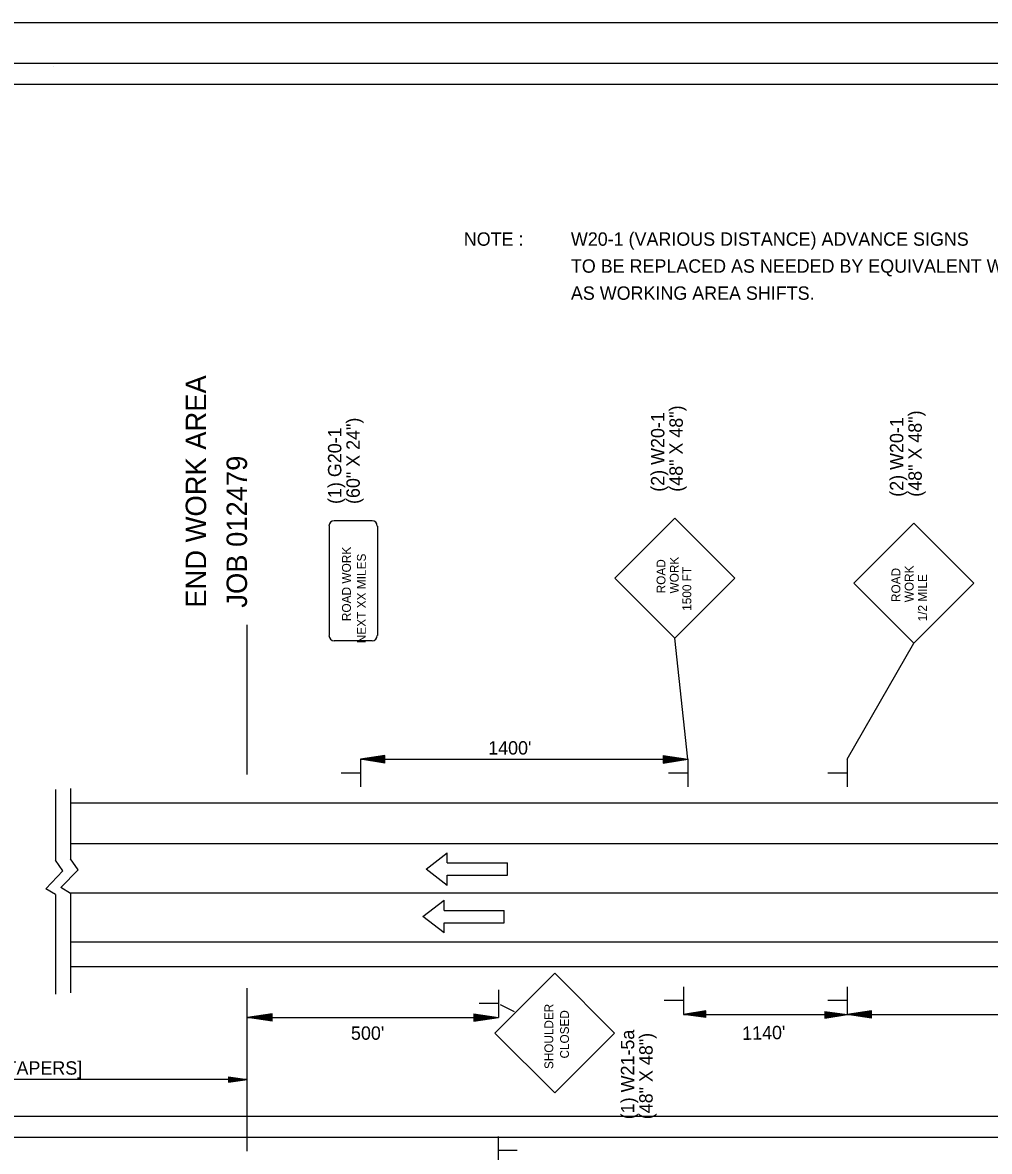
# Model space of a CAD drawing. Extents: x 1373222 to 1374279, y 380783 to 380996.
# Drawn here: x 1373384 to 1373476.4, y 380888.5 to 380996.5 of the extents above; entities that cross this region are included whole.
import ezdxf

# ---------------------------------------------------------------- set-up
doc = ezdxf.new("R2010")
doc.units = 0
for name, color, linetype in [('R_Border', 7, 'Continuous'), ('R_Border Plan-Plan', 7, 'Continuous'), ('R_Draft', 7, 'Continuous'), ('R_No Plot', 7, 'Continuous')]:
    doc.layers.add(name, color=color, linetype=linetype)

msp = doc.modelspace()

# ---------------------------------------------------------------- linework, layer by layer
at = {"layer": 'R_Border'}
for p, q in [((1373234.38, 380992.59), (1373550.56, 380992.59)), ((1373386.9, 380992.33), (1373386.9, 380992.33)), ((1373386.9, 380992.33), (1373386.9, 380992.33))]:
    msp.add_line(p, q, dxfattribs=at)
at = {"layer": 'R_Border Plan-Plan'}
msp.add_line((1373234.38, 380889.86), (1373550.56, 380889.86), dxfattribs=at)
at = {"layer": 'R_Draft'}
for p, q in [((1373417.39, 380948.84), (1373413.78, 380948.84)), ((1373446.36, 380949.08), (1373440.62, 380943.35)), ((1373446.36, 380949.08), (1373452.09, 380943.35)), ((1373469.2, 380948.61), (1373463.47, 380942.88)), ((1373469.2, 380948.61), (1373474.93, 380942.88)), ((1373413.28, 380948.33), (1373413.28, 380937.85)), ((1373417.9, 380948.33), (1373417.9, 380937.85)), ((1373440.62, 380943.35), (1373446.36, 380937.61)), ((1373452.09, 380943.35), (1373446.36, 380937.61)), ((1373463.47, 380942.88), (1373469.2, 380937.14)), ((1373474.93, 380942.88), (1373469.2, 380937.14)), ((1373405.44, 380924.56), (1373405.44, 380938.87)), ((1373417.39, 380937.35), (1373413.78, 380937.35)), ((1373447.58, 380926.02), (1373446.36, 380937.61)), ((1373462.83, 380926.02), (1373469.2, 380937.14)), ((1373418.63, 380926.37), (1373416.28, 380926.02)), ((1373416.28, 380926.02), (1373416.28, 380923.38)), ((1373416.28, 380926.02), (1373447.58, 380926.02)), ((1373418.63, 380925.66), (1373416.28, 380926.02)), ((1373418.63, 380926.31), (1373416.67, 380926.02)), ((1373418.63, 380925.72), (1373416.67, 380926.02)), ((1373418.63, 380926.25), (1373417.08, 380926.02)), ((1373418.63, 380925.78), (1373417.08, 380926.02)), ((1373418.63, 380926.19), (1373417.47, 380926.02)), ((1373418.63, 380925.84), (1373417.47, 380926.02)), ((1373418.63, 380926.13), (1373417.87, 380926.02)), ((1373418.63, 380925.9), (1373417.87, 380926.02)), ((1373418.63, 380926.07), (1373418.26, 380926.02)), ((1373418.63, 380925.96), (1373418.26, 380926.02)), ((1373418.63, 380925.66), (1373418.63, 380926.37)), ((1373445.23, 380926.37), (1373447.58, 380926.02)), ((1373445.23, 380926.37), (1373445.23, 380925.66)), ((1373445.23, 380926.31), (1373447.18, 380926.02)), ((1373445.23, 380926.25), (1373446.78, 380926.02)), ((1373445.23, 380926.19), (1373446.39, 380926.02)), ((1373445.23, 380926.13), (1373445.99, 380926.02)), ((1373445.23, 380926.07), (1373445.6, 380926.02)), ((1373445.23, 380925.66), (1373447.58, 380926.02)), ((1373445.23, 380925.9), (1373445.99, 380926.02)), ((1373445.23, 380925.78), (1373446.78, 380926.02)), ((1373445.23, 380925.72), (1373447.18, 380926.02)), ((1373445.23, 380925.84), (1373446.39, 380926.02)), ((1373445.23, 380925.96), (1373445.6, 380926.02)), ((1373447.58, 380926.02), (1373447.58, 380923.38)), ((1373462.83, 380926.02), (1373462.83, 380923.38)), ((1373416.24, 380924.7), (1373414.44, 380924.7)), ((1373447.54, 380924.7), (1373445.74, 380924.7)), ((1373462.79, 380924.7), (1373460.99, 380924.7)), ((1373387.11, 380923.14), (1373387.11, 380916.38)), ((1373388.56, 380923.24), (1373388.56, 380916.49)), ((1373407.82, 380921.83), (1373388.56, 380921.83)), ((1373492.92, 380921.83), (1373407.82, 380921.83)), ((1373407.82, 380917.92), (1373388.56, 380917.92)), ((1373492.92, 380917.92), (1373407.82, 380917.92)), ((1373422.56, 380915.51), (1373424.59, 380917.07)), ((1373424.59, 380916.1), (1373424.59, 380917.07)), ((1373424.59, 380916.1), (1373430.34, 380916.1)), ((1373430.34, 380914.92), (1373430.34, 380916.1)), ((1373424.59, 380913.95), (1373422.56, 380915.51)), ((1373424.59, 380914.92), (1373430.34, 380914.92)), ((1373424.59, 380913.95), (1373424.59, 380914.92)), ((1373387.11, 380913.09), (1373387.11, 380903.56)), ((1373407.82, 380913.22), (1373388.5, 380913.22)), ((1373388.56, 380913.19), (1373388.56, 380903.67)), ((1373492.92, 380913.22), (1373407.82, 380913.22)), ((1373422.25, 380910.98), (1373424.28, 380912.54)), ((1373424.28, 380911.56), (1373424.28, 380912.54)), ((1373424.28, 380909.41), (1373422.25, 380910.98)), ((1373424.28, 380911.56), (1373430.04, 380911.56)), ((1373430.04, 380910.39), (1373430.04, 380911.56)), ((1373424.28, 380910.39), (1373430.04, 380910.39)), ((1373424.28, 380909.41), (1373424.28, 380910.39)), ((1373407.82, 380908.53), (1373388.56, 380908.53)), ((1373492.92, 380908.53), (1373407.82, 380908.53)), ((1373407.82, 380906.18), (1373388.56, 380906.18)), ((1373492.92, 380906.18), (1373407.82, 380906.18)), ((1373434.86, 380905.57), (1373429.13, 380899.83)), ((1373434.86, 380905.57), (1373440.59, 380899.83)), ((1373447.18, 380904.25), (1373447.18, 380901.61)), ((1373462.83, 380904.25), (1373462.83, 380901.61)), ((1373405.44, 380888.52), (1373405.44, 380904.12)), ((1373429.48, 380903.97), (1373429.48, 380901.33)), ((1373429.44, 380902.66), (1373427.64, 380902.66)), ((1373429.65, 380902.57), (1373431, 380901.88)), ((1373447.14, 380902.94), (1373445.34, 380902.94)), ((1373462.79, 380902.94), (1373460.99, 380902.94)), ((1373407.83, 380901.68), (1373405.48, 380901.33)), ((1373405.48, 380901.33), (1373429.48, 380901.33)), ((1373407.83, 380900.98), (1373405.48, 380901.33)), ((1373407.83, 380901.62), (1373405.87, 380901.33)), ((1373407.83, 380901.04), (1373405.87, 380901.33)), ((1373407.83, 380901.56), (1373406.28, 380901.33)), ((1373407.83, 380901.1), (1373406.28, 380901.33)), ((1373407.83, 380901.5), (1373406.67, 380901.33)), ((1373407.83, 380901.15), (1373406.67, 380901.33)), ((1373407.83, 380901.44), (1373407.07, 380901.33)), ((1373407.83, 380901.22), (1373407.07, 380901.33)), ((1373407.83, 380901.38), (1373407.46, 380901.33)), ((1373407.83, 380901.27), (1373407.46, 380901.33)), ((1373407.83, 380900.98), (1373407.83, 380901.68)), ((1373427.13, 380901.68), (1373429.48, 380901.33)), ((1373427.13, 380901.68), (1373427.13, 380900.98)), ((1373427.13, 380901.62), (1373429.09, 380901.33)), ((1373427.13, 380901.56), (1373428.68, 380901.33)), ((1373427.13, 380901.5), (1373428.29, 380901.33)), ((1373427.13, 380901.44), (1373427.89, 380901.33)), ((1373427.13, 380901.38), (1373427.5, 380901.33)), ((1373427.13, 380900.98), (1373429.48, 380901.33)), ((1373427.13, 380901.21), (1373427.89, 380901.33)), ((1373427.13, 380901.1), (1373428.68, 380901.33)), ((1373427.13, 380901.04), (1373429.09, 380901.33)), ((1373427.13, 380901.15), (1373428.29, 380901.33)), ((1373427.13, 380901.27), (1373427.5, 380901.33)), ((1373449.31, 380901.96), (1373447.18, 380901.61)), ((1373447.18, 380901.61), (1373462.83, 380901.61)), ((1373449.32, 380901.32), (1373447.18, 380901.61)), ((1373449.31, 380901.91), (1373447.54, 380901.61)), ((1373449.32, 380901.38), (1373447.54, 380901.61)), ((1373449.31, 380901.85), (1373447.9, 380901.62)), ((1373449.32, 380901.43), (1373447.9, 380901.62)), ((1373449.31, 380901.8), (1373448.26, 380901.63)), ((1373449.31, 380901.48), (1373448.26, 380901.63)), ((1373449.31, 380901.75), (1373448.62, 380901.63)), ((1373449.31, 380901.54), (1373448.62, 380901.63)), ((1373449.31, 380901.69), (1373448.98, 380901.64)), ((1373449.31, 380901.59), (1373448.98, 380901.64)), ((1373449.32, 380901.32), (1373449.31, 380901.96)), ((1373460.69, 380901.89), (1373462.83, 380901.61)), ((1373460.69, 380901.89), (1373460.7, 380901.25)), ((1373460.69, 380901.84), (1373462.47, 380901.6)), ((1373460.69, 380901.79), (1373462.1, 380901.6)), ((1373460.69, 380901.73), (1373461.75, 380901.59)), ((1373460.69, 380901.68), (1373461.39, 380901.59)), ((1373460.69, 380901.62), (1373461.03, 380901.58)), ((1373460.69, 380901.47), (1373461.39, 380901.59)), ((1373460.69, 380901.42), (1373461.75, 380901.59)), ((1373460.69, 380901.52), (1373461.03, 380901.58)), ((1373460.7, 380901.25), (1373462.83, 380901.61)), ((1373460.7, 380901.36), (1373462.1, 380901.6)), ((1373460.7, 380901.31), (1373462.47, 380901.6)), ((1373465.17, 380901.96), (1373462.83, 380901.61)), ((1373462.83, 380901.61), (1373497.83, 380901.61)), ((1373465.17, 380901.26), (1373462.83, 380901.61)), ((1373465.17, 380901.9), (1373463.22, 380901.61)), ((1373465.17, 380901.31), (1373463.22, 380901.61)), ((1373465.17, 380901.84), (1373463.62, 380901.61)), ((1373465.17, 380901.38), (1373463.62, 380901.61)), ((1373465.17, 380901.78), (1373464.01, 380901.61)), ((1373465.17, 380901.43), (1373464.01, 380901.61)), ((1373465.17, 380901.72), (1373464.41, 380901.61)), ((1373465.17, 380901.49), (1373464.41, 380901.61)), ((1373465.17, 380901.66), (1373464.8, 380901.61)), ((1373465.17, 380901.55), (1373464.8, 380901.61)), ((1373465.17, 380901.26), (1373465.17, 380901.96)), ((1373429.13, 380899.83), (1373434.86, 380894.1)), ((1373440.59, 380899.83), (1373434.86, 380894.1)), ((1373403.67, 380895.66), (1373405.44, 380895.39)), ((1373403.67, 380895.66), (1373403.67, 380895.13)), ((1373403.67, 380895.62), (1373405.15, 380895.39)), ((1373403.67, 380895.57), (1373404.84, 380895.39)), ((1373405.44, 380895.39), (1373345.02, 380895.39)), ((1373403.67, 380895.53), (1373404.54, 380895.39)), ((1373403.67, 380895.48), (1373404.24, 380895.39)), ((1373403.67, 380895.44), (1373403.95, 380895.39)), ((1373403.67, 380895.13), (1373405.44, 380895.39)), ((1373403.67, 380895.31), (1373404.24, 380895.39)), ((1373403.67, 380895.22), (1373404.84, 380895.39)), ((1373403.67, 380895.17), (1373405.15, 380895.39)), ((1373403.67, 380895.26), (1373404.54, 380895.39)), ((1373403.67, 380895.35), (1373403.95, 380895.39)), ((1373429.44, 380889.95), (1373429.44, 380887.31)), ((1373429.47, 380888.64), (1373431.28, 380888.64))]:
    msp.add_line(p, q, dxfattribs=at)
for points in [[(1373387.11, 380913.09), (1373386.19, 380913.64), (1373387.84, 380915.35), (1373387.11, 380916.38)], [(1373388.56, 380913.19), (1373387.63, 380913.75), (1373389.28, 380915.45), (1373388.56, 380916.49)]]:
    msp.add_lwpolyline(points, dxfattribs=at)
for centre, start, end in [((1373413.78, 380948.33), 90, 180), ((1373417.39, 380948.33), 360, 90), ((1373413.78, 380937.85), 180, 270), ((1373417.39, 380937.85), 270, 360)]:
    msp.add_arc(centre, 0.505, start, end, dxfattribs=at)
at = {"layer": 'R_No Plot'}
for points in [[(1373221.98, 380996.49), (1373555.32, 380996.49), (1373555.32, 380783.15), (1373221.98, 380783.15)], [(1373548.56, 380891.86), (1373236.38, 380891.86), (1373236.38, 380990.59), (1373485.92, 380990.59), (1373485.92, 380980.71), (1373503.46, 380980.71), (1373527.56, 380980.71), (1373527.56, 380958.38), (1373548.56, 380958.38)], [(1373236.38, 380990.59), (1373485.92, 380990.59), (1373485.92, 380980.71), (1373503.46, 380980.71), (1373527.56, 380980.71), (1373527.56, 380958.38), (1373548.56, 380958.38), (1373548.56, 380789.13), (1373236.38, 380789.13)]]:
    msp.add_lwpolyline(points, close=True, dxfattribs=at)

# ---------------------------------------------------------------- texts
at = {"layer": 'R_Draft'}
for s, p in [('NOTE : ', (1373426.17, 380975.14)), ('W20-1 (VARIOUS DISTANCE) ADVANCE SIGNS', (1373436.41, 380975.14)), ('TO BE REPLACED AS NEEDED BY EQUIVALENT W20-5 SIGNS', (1373436.41, 380972.56)), ('AS WORKING AREA SHIFTS.', (1373436.41, 380969.97)), ('[MAXIMUM EXTENT OF LANE CLOSURE TAPERS]', (1373349.35, 380895.85))]:
    msp.add_text(s, height=1.28, dxfattribs=at).set_placement(p)
for s, height, rotation, p in [('END WORK AREA', 1.9558, 90, (1373401.53, 380940.52)), ('(48" X 48")', 1.28, 90, (1373447.11, 380951.61)), ('(48" X 48")', 1.28, 90, (1373469.96, 380951.13)), ('(60" X 24")', 1.28, 90, (1373416.22, 380950.44)), ('(2) W20-1', 1.28, 90, (1373445.35, 380951.61)), ('(2) W20-1', 1.28, 90, (1373468.2, 380951.13)), ('(1) G20-1', 1.28, 90, (1373414.46, 380950.44)), ('JOB 012479', 1.956, 90, (1373405.44, 380940.52)), ('ROAD WORK', 0.848, 90, (1373415.37, 380939.23)), (' NEXT XX MILES', 0.8486, 90, (1373416.8, 380936.8)), ('WORK', 0.845, 90, (1373446.72, 380941.88)), ('ROAD', 0.845, 90.0004, (1373445.45, 380941.89)), ('1500 FT', 0.845, 90.0004, (1373447.92, 380940.22)), ('ROAD', 0.845, 90.0004, (1373467.91, 380941.06)), ('WORK', 0.845, 90, (1373469.18, 380941.04)), ('1/2 MILE', 0.845, 90, (1373470.46, 380939.21)), ("1400'", 1.28, 360, (1373428.5, 380926.47)), ('SHOULDER', 0.84, 90, (1373434.72, 380896.39)), ('CLOSED', 0.84, 90.0004, (1373436.22, 380897.4)), ("500'", 1.28, 360, (1373415.38, 380899.19)), ('(1) W21-5a', 1.28, 90, (1373442.47, 380891.59)), ("1140'", 1.28, 1.2304, (1373452.8, 380899.17)), ('(48" X 48")', 1.28, 90, (1373444.23, 380891.59))]:
    msp.add_text(s, height=height, rotation=rotation, dxfattribs=at).set_placement(p)

doc.saveas('drawing.dxf')
